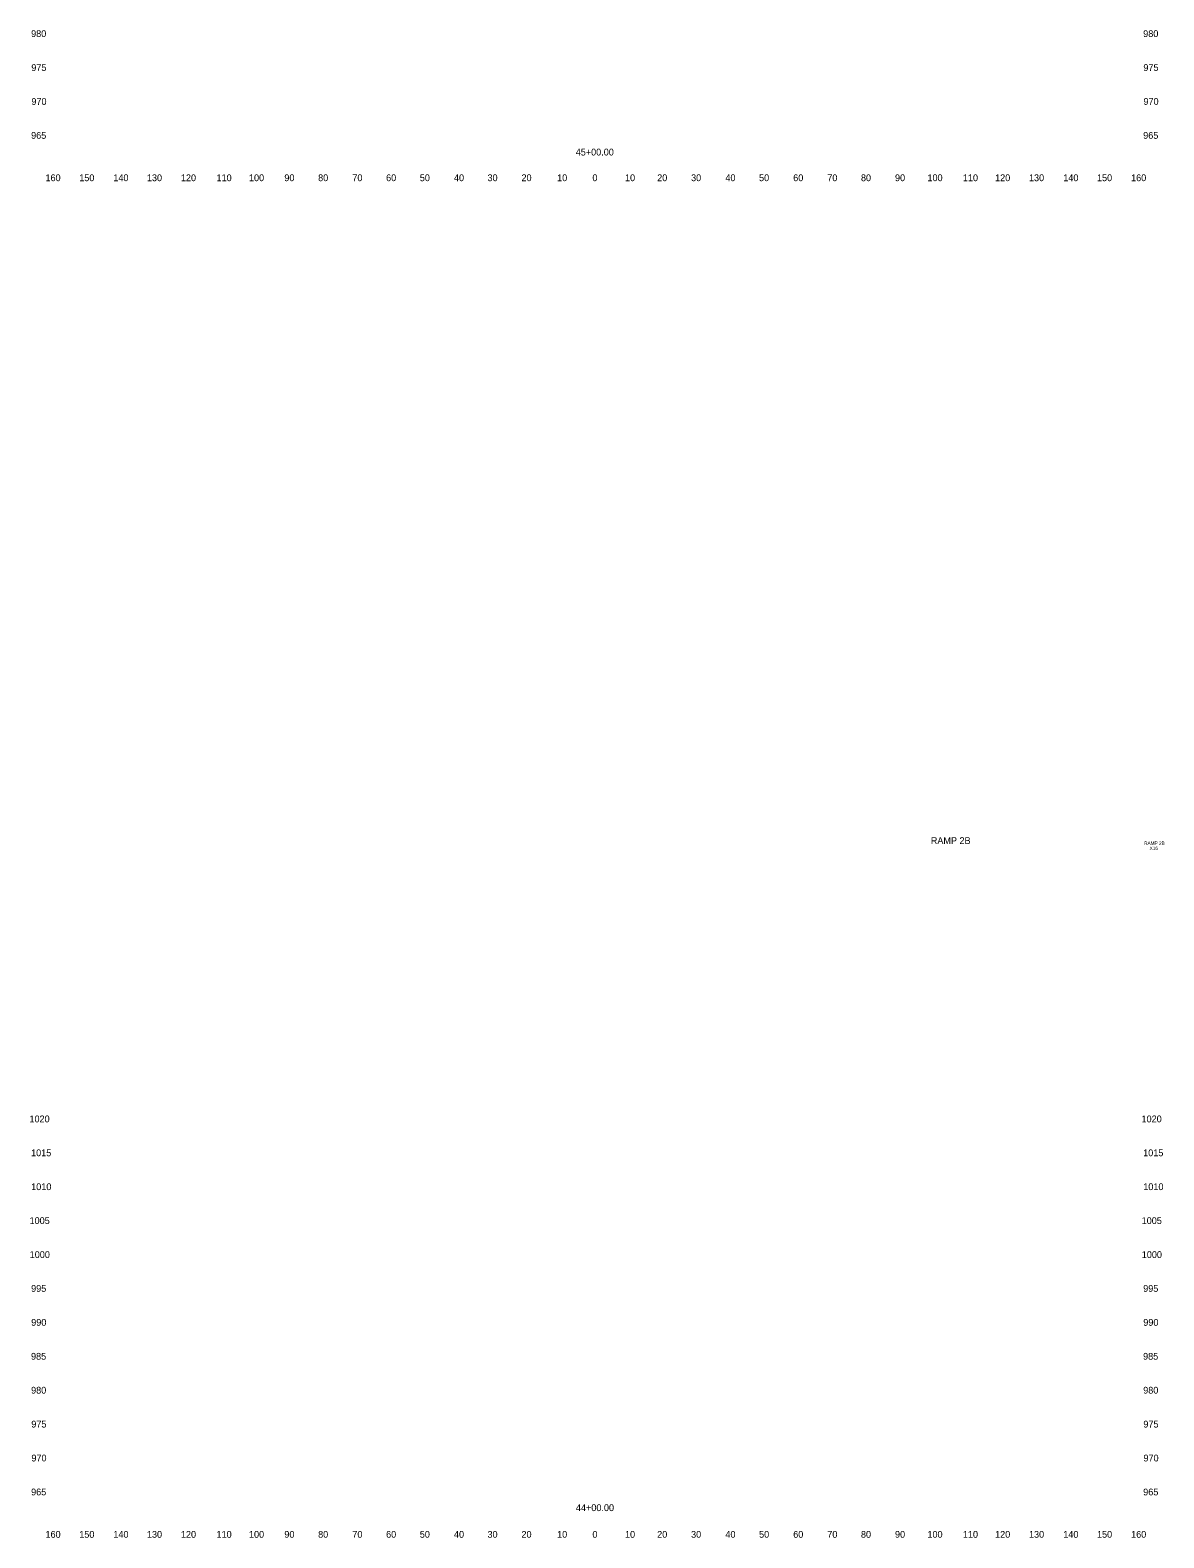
# Model space of a CAD drawing. Extents: x 4994 to 6358, y 4997 to 8804.
# Drawn here: x 5508.6 to 5842.7, y 6997.5 to 7442 of the extents above; entities that cross this region are included whole.
import ezdxf

# ---------------------------------------------------------------- set-up
doc = ezdxf.new("R2010")
doc.units = 0
for name, color, linetype in [('RD_SHT_ID', 7, 'Continuous'), ('RD_XS_TX_Offset', 7, 'Continuous'), ('RD_XS_TX_Station', 7, 'Continuous')]:
    doc.layers.add(name, color=color, linetype=linetype)

msp = doc.modelspace()

# ---------------------------------------------------------------- texts
at = {"layer": 'RD_SHT_ID'}
for s, height, p in [('RAMP 2B', 2, (5774.05, 7202.06)), ('RAMP 2B', 1, (5836.94, 7201.8)), ('X16', 1, (5838.55, 7200.3))]:
    msp.add_text(s, height=height, dxfattribs=at).set_placement(p)
at = {"layer": 'RD_XS_TX_Offset'}
for s, p in [('980', (5508.86, 7440)), ('980', (5836.66, 7440)), ('975', (5508.91, 7430)), ('975', (5836.71, 7430)), ('970', (5508.94, 7420)), ('970', (5836.74, 7420)), ('965', (5508.86, 7410)), ('965', (5836.66, 7410)), ('160', (5513.1, 7397.5)), ('150', (5523.04, 7397.5)), ('140', (5533.1, 7397.5)), ('130', (5542.99, 7397.5)), ('120', (5553.01, 7397.5)), ('110', (5563.51, 7397.5)), ('100', (5573.07, 7397.5)), ('90', (5583.5, 7397.5)), ('80', (5593.46, 7397.5)), ('70', (5603.54, 7397.5)), ('60', (5613.5, 7397.5)), ('50', (5623.43, 7397.5)), ('40', (5633.5, 7397.5)), ('30', (5643.39, 7397.5)), ('20', (5653.4, 7397.5)), ('10', (5663.91, 7397.5)), ('0', (5674.3, 7397.5)), ('0', (5674.3, 7397.5)), ('10', (5683.91, 7397.5)), ('20', (5693.4, 7397.5)), ('30', (5703.39, 7397.5)), ('40', (5713.5, 7397.5)), ('50', (5723.43, 7397.5)), ('60', (5733.5, 7397.5)), ('70', (5743.54, 7397.5)), ('80', (5753.46, 7397.5)), ('90', (5763.5, 7397.5)), ('100', (5773.07, 7397.5)), ('110', (5783.51, 7397.5)), ('120', (5793.01, 7397.5)), ('130', (5802.99, 7397.5)), ('140', (5813.1, 7397.5)), ('150', (5823.04, 7397.5)), ('160', (5833.1, 7397.5)), ('1020', (5508.37, 7120)), ('1020', (5836.17, 7120)), ('1015', (5508.85, 7110)), ('1015', (5836.65, 7110)), ('1010', (5508.88, 7100)), ('1010', (5836.68, 7100)), ('1005', (5508.4, 7090)), ('1005', (5836.2, 7090)), ('1000', (5508.44, 7080)), ('1000', (5836.24, 7080)), ('995', (5508.86, 7070)), ('995', (5836.66, 7070)), ('990', (5508.89, 7060)), ('990', (5836.69, 7060)), ('985', (5508.83, 7050)), ('985', (5836.63, 7050)), ('980', (5508.86, 7040)), ('980', (5836.66, 7040)), ('975', (5508.91, 7030)), ('975', (5836.71, 7030)), ('970', (5508.94, 7020)), ('970', (5836.74, 7020)), ('965', (5508.86, 7010)), ('965', (5836.66, 7010)), ('160', (5513.1, 6997.5)), ('150', (5523.04, 6997.5)), ('140', (5533.1, 6997.5)), ('130', (5542.99, 6997.5)), ('120', (5553.01, 6997.5)), ('110', (5563.51, 6997.5)), ('100', (5573.07, 6997.5)), ('90', (5583.5, 6997.5)), ('80', (5593.46, 6997.5)), ('70', (5603.54, 6997.5)), ('60', (5613.5, 6997.5)), ('50', (5623.43, 6997.5)), ('40', (5633.5, 6997.5)), ('30', (5643.39, 6997.5)), ('20', (5653.4, 6997.5)), ('10', (5663.91, 6997.5)), ('0', (5674.3, 6997.5)), ('0', (5674.3, 6997.5)), ('10', (5683.91, 6997.5)), ('20', (5693.4, 6997.5)), ('30', (5703.39, 6997.5)), ('40', (5713.5, 6997.5)), ('50', (5723.43, 6997.5)), ('60', (5733.5, 6997.5)), ('70', (5743.54, 6997.5)), ('80', (5753.46, 6997.5)), ('90', (5763.5, 6997.5)), ('100', (5773.07, 6997.5)), ('110', (5783.51, 6997.5)), ('120', (5793.01, 6997.5)), ('130', (5802.99, 6997.5)), ('140', (5813.1, 6997.5)), ('150', (5823.04, 6997.5)), ('160', (5833.1, 6997.5))]:
    msp.add_text(s, height=2, dxfattribs=at).set_placement(p)
at = {"layer": 'RD_XS_TX_Station'}
for s, p in [('45+00.00', (5669.39, 7405.07)), ('44+00.00', (5669.45, 7005.36))]:
    msp.add_text(s, height=2, dxfattribs=at).set_placement(p)

doc.saveas('drawing.dxf')
